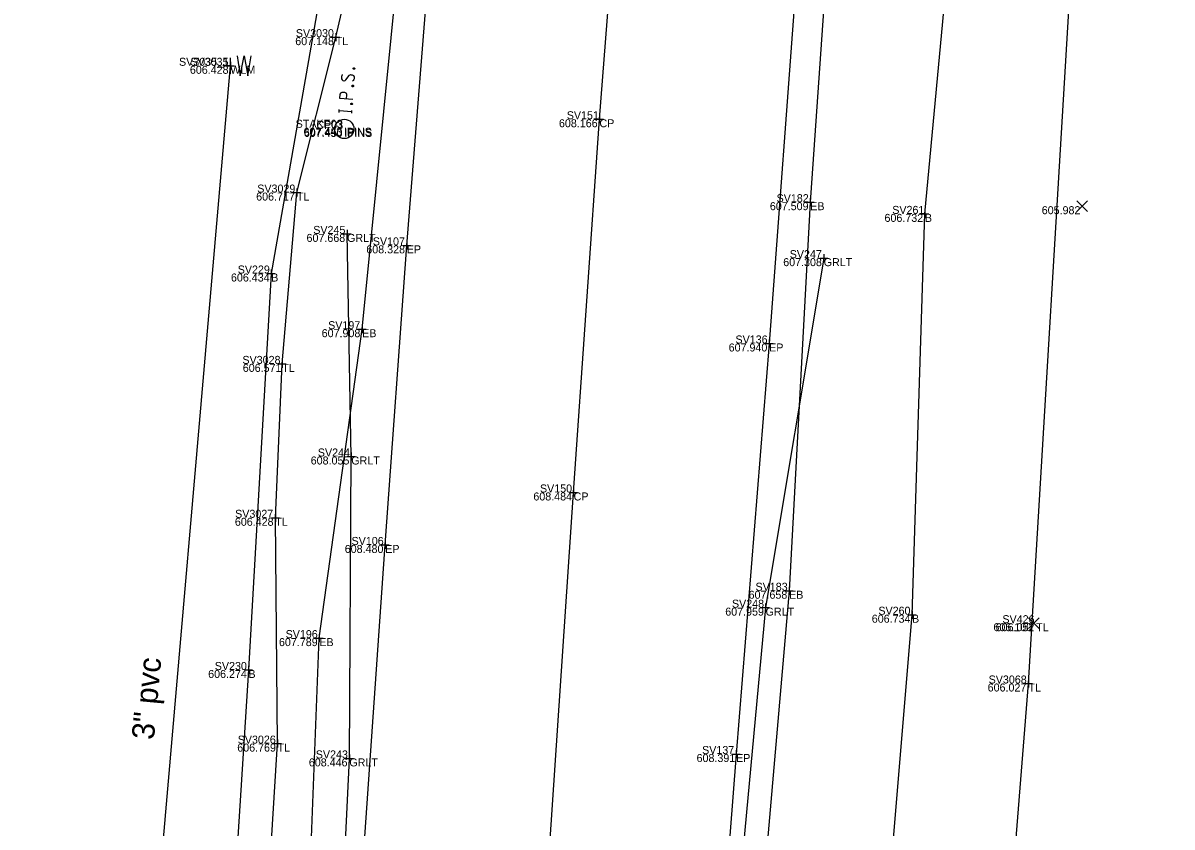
# Model space of a CAD drawing. Extents: x -2 to 1979875, y -2 to 232027.
# Drawn here: x 1978751.3 to 1978823.1, y 231412.1 to 231462.4 of the extents above; entities that cross this region are included whole.
import ezdxf

# ---------------------------------------------------------------- set-up
doc = ezdxf.new("R2010")
doc.units = 0
for name, color, linetype in [('_CIVIL_CONSTRUCTION', 7, 'Continuous'), ('GE_P_Alignment', 7, 'Continuous'), ('GE_P_Alignment_1000_Curve_Data', 7, 'Continuous'), ('GE_P_Alignment_100_Curve_Data', 7, 'Continuous'), ('GE_X_Alignment', 7, 'Continuous'), ('GE_X_Alignment_1000_Curve_Data', 7, 'Continuous'), ('GE_X_Alignment_1000_Stations', 7, 'Continuous'), ('GE_X_Alignment_100_Curve_Data', 7, 'Continuous'), ('GE_X_Alignment_100_Stations', 7, 'Continuous'), ('RW_X_CL', 7, 'Continuous'), ('SC_Scratch1', 7, 'Continuous'), ('SV_X_Random_Point', 7, 'Continuous'), ('UT_X_Water', 7, 'Continuous'), ('UT_X_Water_Cells', 7, 'Continuous'), ('UT_X_Water_Text', 7, 'Continuous')]:
    doc.layers.add(name, color=color, linetype=linetype)

msp = doc.modelspace()

# ---------------------------------------------------------------- linework, layer by layer
at = {"layer": 'GE_P_Alignment'}
for points in [[(1978861.689, 231782.415), (1978851.853, 231763.969), (1978841.987, 231745.294), (1978832.802, 231726.204), (1978823.63, 231707.125), (1978815.734, 231686.751), (1978809.08, 231664.461), (1978799.472, 231640.53), (1978791.914, 231616.771), (1978786.956, 231593.117), (1978782.497, 231568.131), (1978778.452, 231542.695), (1978775.331, 231517.531), (1978773.11, 231494.147), (1978771.443, 231473.021), (1978766.839, 231446.726), (1978765.415, 231421.944), (1978763.995, 231399.725), (1978762.317, 231376.717), (1978760.52, 231353.776), (1978758.484, 231331.627), (1978756.746, 231315.247), (1978755.236, 231305.004), (1978757.214, 231296.936)], [(1978796.543, 231298.857), (1978798.274, 231324.443), (1978800.704, 231350.055), (1978802.691, 231376.873), (1978804.911, 231401.653), (1978806.885, 231425.398), (1978807.692, 231450.453), (1978809.926, 231474.524), (1978811.781, 231491.704), (1978814.624, 231521.225), (1978818.445, 231546.214), (1978822.849, 231572.066), (1978827.059, 231594.68), (1978834.582, 231618.811), (1978841.486, 231643.192), (1978848.448, 231666.52), (1978859.661, 231691.186), (1978869.566, 231712.589), (1978880.404, 231735.407), (1978890.398, 231756.483), (1978895.241, 231765.92)]]:
    msp.add_lwpolyline(points, dxfattribs=at)
at = {"layer": 'GE_P_Alignment_1000_Curve_Data'}
for points in [[(1978733.125, 231254.651), (1978737.318, 231281.706), (1978740.694, 231296.926), (1978742.413, 231306.837), (1978748.228, 231322.336), (1978755.317, 231333.122), (1978758.78, 231344.165), (1978763.011, 231368.433), (1978764.4, 231379.716), (1978765.858, 231395.082), (1978767.238, 231417.341), (1978767.097, 231431.457), (1978767.532, 231441.077), (1978768.449, 231451.786), (1978770.871, 231461.5), (1978774.002, 231474.92), (1978775.889, 231489.026), (1978776.895, 231504.336), (1978777.94, 231514.653)], [(1978800.253, 231250.204), (1978805.284, 231291.391), (1978804.508, 231297.592), (1978804.78, 231306.073), (1978804.463, 231312.372), (1978805.146, 231324.315), (1978805.161, 231336.373), (1978807.189, 231350.111), (1978807.848, 231360.671), (1978809.086, 231373.348), (1978811.125, 231382.982), (1978814.162, 231421.098), (1978816.965, 231468.048), (1978822.427, 231510.515)]]:
    msp.add_lwpolyline(points, dxfattribs=at)
at = {"layer": 'GE_P_Alignment_100_Curve_Data'}
for points in [[(1978764.438, 231298.773), (1978765.712, 231320.829), (1978767.378, 231345.616), (1978768.807, 231367.39), (1978770.554, 231391.673), (1978771.722, 231416.416), (1978771.842, 231435.288), (1978771.576, 231449.202)], [(1978801.365, 231447.686), (1978797.734, 231425.84), (1978795.609, 231402.949), (1978794.056, 231378.448), (1978792.74, 231353.579), (1978790.842, 231329.19), (1978789.312, 231307.337), (1978788.697, 231297.789)]]:
    msp.add_lwpolyline(points, dxfattribs=at)
at = {"layer": 'GE_X_Alignment_1000_Curve_Data'}
msp.add_lwpolyline([(1978776.88, 231293.019), (1978778.313, 231315.451), (1978779.686, 231337.763), (1978781.119, 231360.475), (1978782.569, 231384.073), (1978784.079, 231408.548), (1978785.737, 231433.04), (1978787.352, 231456.369), (1978789.204, 231480.117), (1978791.477, 231503.648), (1978794.349, 231526.784), (1978797.796, 231550.891), (1978801.515, 231572.898), (1978806.442, 231596.208), (1978812.098, 231619.057), (1978818.629, 231640.775), (1978826, 231662.112), (1978835.057, 231685.412), (1978844.843, 231707.874), (1978854.489, 231728.841), (1978864.575, 231749.812), (1978877.222, 231774.568)], dxfattribs=at)
at = {"layer": 'GE_X_Alignment_1000_Stations'}
for points in [[(1978764.463, 231293.7), (1978765.973, 231315.536), (1978767.501, 231337.797), (1978768.95, 231360.619), (1978770.673, 231383.826), (1978772.372, 231407.034), (1978773.964, 231429.759), (1978775.312, 231448.487), (1978777.194, 231472.049), (1978779.086, 231494.381), (1978781.387, 231516.708), (1978784.451, 231540.773), (1978787.814, 231562.2), (1978793.416, 231590.474), (1978799.132, 231614.141), (1978805.307, 231636.271), (1978811.99, 231656.714), (1978821.006, 231681.034), (1978832.082, 231707.98), (1978843.434, 231732.641), (1978854.786, 231756.844), (1978866.633, 231780.181)], [(1978887.054, 231769.497), (1978875.688, 231747.111), (1978865.322, 231725.635), (1978856.257, 231705.079), (1978847.493, 231684.376), (1978839.463, 231663.377), (1978831.793, 231640.155), (1978824.647, 231616.117), (1978817.773, 231591.521), (1978812.873, 231567.295), (1978809.011, 231544.227), (1978805.416, 231519.882), (1978802.367, 231496.191), (1978799.68, 231465.625), (1978797.956, 231442.353), (1978795.891, 231416.691), (1978793.937, 231391.428), (1978792.627, 231370.424), (1978791.336, 231345.811), (1978789.97, 231322.684), (1978787.965, 231301.579), (1978787.711, 231292.48)]]:
    msp.add_lwpolyline(points, dxfattribs=at)
at = {"layer": 'GE_X_Alignment_100_Curve_Data'}
for p, q in [((1978770.871, 231461.75), (1978770.871, 231461.25)), ((1978770.621, 231461.5), (1978771.121, 231461.5)), ((1978770.871, 231461.5), (1978770.871, 231461.5)), ((1978764.036, 231459.71), (1978764.536, 231459.71)), ((1978764.286, 231459.96), (1978764.286, 231459.46)), ((1978764.286, 231459.71), (1978764.286, 231459.71)), ((1978787.102, 231456.369), (1978787.602, 231456.369)), ((1978787.352, 231456.619), (1978787.352, 231456.119)), ((1978787.352, 231456.369), (1978787.352, 231456.369)), ((1978768.199, 231451.786), (1978768.699, 231451.786)), ((1978768.449, 231452.036), (1978768.449, 231451.536)), ((1978768.449, 231451.786), (1978768.449, 231451.786)), ((1978800.271, 231451.185), (1978800.771, 231451.185)), ((1978800.521, 231451.435), (1978800.521, 231450.935)), ((1978800.521, 231451.185), (1978800.521, 231451.185)), ((1978807.442, 231450.453), (1978807.942, 231450.453)), ((1978807.692, 231450.703), (1978807.692, 231450.203)), ((1978807.692, 231450.453), (1978807.692, 231450.453)), ((1978771.576, 231449.452), (1978771.576, 231448.952)), ((1978771.326, 231449.202), (1978771.826, 231449.202)), ((1978771.576, 231449.202), (1978771.576, 231449.202)), ((1978775.312, 231448.737), (1978775.312, 231448.237)), ((1978775.062, 231448.487), (1978775.562, 231448.487)), ((1978775.312, 231448.487), (1978775.312, 231448.487)), ((1978801.115, 231447.686), (1978801.615, 231447.686)), ((1978801.365, 231447.936), (1978801.365, 231447.436)), ((1978801.365, 231447.686), (1978801.365, 231447.686)), ((1978766.589, 231446.726), (1978767.089, 231446.726)), ((1978766.839, 231446.976), (1978766.839, 231446.476)), ((1978766.839, 231446.726), (1978766.839, 231446.726)), ((1978772.272, 231443.246), (1978772.772, 231443.246)), ((1978772.522, 231443.496), (1978772.522, 231442.996)), ((1978772.522, 231443.246), (1978772.522, 231443.246)), ((1978797.706, 231442.353), (1978798.206, 231442.353)), ((1978797.956, 231442.603), (1978797.956, 231442.103)), ((1978797.956, 231442.353), (1978797.956, 231442.353)), ((1978767.282, 231441.077), (1978767.782, 231441.077)), ((1978767.532, 231441.327), (1978767.532, 231440.827)), ((1978767.532, 231441.077), (1978767.532, 231441.077)), ((1978771.592, 231435.288), (1978772.092, 231435.288)), ((1978771.842, 231435.538), (1978771.842, 231435.038)), ((1978771.842, 231435.288), (1978771.842, 231435.288)), ((1978785.487, 231433.04), (1978785.987, 231433.04)), ((1978785.737, 231433.29), (1978785.737, 231432.79)), ((1978785.737, 231433.04), (1978785.737, 231433.04)), ((1978767.097, 231431.707), (1978767.097, 231431.207)), ((1978766.847, 231431.457), (1978767.347, 231431.457)), ((1978767.097, 231431.457), (1978767.097, 231431.457)), ((1978773.714, 231429.759), (1978774.214, 231429.759)), ((1978773.964, 231430.009), (1978773.964, 231429.509)), ((1978773.964, 231429.759), (1978773.964, 231429.759)), ((1978798.953, 231426.897), (1978799.453, 231426.897)), ((1978799.203, 231427.147), (1978799.203, 231426.647)), ((1978799.203, 231426.897), (1978799.203, 231426.897)), ((1978797.484, 231425.84), (1978797.984, 231425.84)), ((1978797.734, 231426.09), (1978797.734, 231425.59)), ((1978797.734, 231425.84), (1978797.734, 231425.84)), ((1978806.635, 231425.398), (1978807.135, 231425.398)), ((1978806.885, 231425.648), (1978806.885, 231425.148)), ((1978806.885, 231425.398), (1978806.885, 231425.398)), ((1978769.594, 231423.935), (1978770.094, 231423.935)), ((1978769.844, 231424.185), (1978769.844, 231423.685)), ((1978769.844, 231423.935), (1978769.844, 231423.935)), ((1978765.415, 231422.194), (1978765.415, 231421.694)), ((1978765.165, 231421.944), (1978765.665, 231421.944)), ((1978765.415, 231421.944), (1978765.415, 231421.944)), ((1978813.912, 231421.098), (1978814.412, 231421.098)), ((1978814.162, 231421.348), (1978814.162, 231420.848)), ((1978814.162, 231421.098), (1978814.162, 231421.098)), ((1978766.988, 231417.341), (1978767.488, 231417.341)), ((1978767.238, 231417.591), (1978767.238, 231417.091)), ((1978767.238, 231417.341), (1978767.238, 231417.341)), ((1978771.722, 231416.666), (1978771.722, 231416.166)), ((1978795.641, 231416.691), (1978796.141, 231416.691)), ((1978795.891, 231416.941), (1978795.891, 231416.441)), ((1978795.891, 231416.691), (1978795.891, 231416.691)), ((1978771.472, 231416.416), (1978771.972, 231416.416)), ((1978771.722, 231416.416), (1978771.722, 231416.416))]:
    msp.add_line(p, q, dxfattribs=at)
at = {"layer": 'RW_X_CL'}
for points in [[(1978771.954, 231459.529), (1978771.955, 231459.556), (1978771.969, 231459.572), (1978771.995, 231459.587), (1978772.027, 231459.585), (1978772.051, 231459.567), (1978772.062, 231459.549), (1978772.06, 231459.522), (1978772.047, 231459.506), (1978772.021, 231459.491), (1978771.989, 231459.493), (1978771.965, 231459.511), (1978771.954, 231459.529)], [(1978771.292, 231459.164), (1978771.278, 231459.154), (1978771.265, 231459.139), (1978771.242, 231459.09), (1978771.226, 231459.031), (1978771.223, 231458.987), (1978771.222, 231458.97), (1978771.236, 231458.897), (1978771.27, 231458.834), (1978771.317, 231458.793), (1978771.367, 231458.778), (1978771.404, 231458.776), (1978771.456, 231458.783), (1978771.502, 231458.824), (1978771.711, 231459.114), (1978771.738, 231459.14), (1978771.764, 231459.149), (1978771.802, 231459.158), (1978771.84, 231459.155), (1978771.878, 231459.147), (1978771.902, 231459.14), (1978771.933, 231459.127), (1978771.957, 231459.114), (1978771.976, 231459.102), (1978771.993, 231459.084), (1978772.005, 231459.067), (1978772.016, 231459.044), (1978772.021, 231459.027), (1978772.024, 231458.977), (1978772.019, 231458.9), (1978772.003, 231458.852), (1978771.954, 231458.783), (1978771.914, 231458.742)], [(1978771.933, 231457.613), (1978771.135, 231457.667), (1978771.152, 231457.931), (1978771.16, 231457.958), (1978771.176, 231457.996), (1978771.189, 231458.011), (1978771.203, 231458.027), (1978771.236, 231458.047), (1978771.268, 231458.061), (1978771.319, 231458.069), (1978771.395, 231458.064), (1978771.419, 231458.057), (1978771.456, 231458.043), (1978771.499, 231458.018), (1978771.516, 231457.995), (1978771.528, 231457.978), (1978771.539, 231457.949), (1978771.542, 231457.905), (1978771.524, 231457.641)], [(1978771.881, 231458.44), (1978771.883, 231458.467), (1978771.896, 231458.483), (1978771.922, 231458.498), (1978771.954, 231458.496), (1978771.978, 231458.478), (1978771.989, 231458.46), (1978771.988, 231458.433), (1978771.974, 231458.417), (1978771.948, 231458.402), (1978771.916, 231458.405), (1978771.892, 231458.423), (1978771.881, 231458.44)], [(1978771.806, 231457.318), (1978771.807, 231457.346), (1978771.821, 231457.361), (1978771.847, 231457.376), (1978771.879, 231457.374), (1978771.903, 231457.356), (1978771.914, 231457.338), (1978771.913, 231457.311), (1978771.899, 231457.295), (1978771.873, 231457.281), (1978771.841, 231457.283), (1978771.817, 231457.301), (1978771.806, 231457.318)], [(1978771.076, 231456.798), (1978771.088, 231456.974)], [(1978771.88, 231456.833), (1978771.082, 231456.886)], [(1978771.875, 231456.745), (1978771.886, 231456.921)]]:
    msp.add_lwpolyline(points, dxfattribs=at)
msp.add_circle((1978771.409, 231455.764), 0.6, dxfattribs=at)
at = {"layer": 'SC_Scratch1'}
for points in [[(1978762.241, 231295.643), (1978763.575, 231312.653), (1978764.638, 231334.283), (1978765.818, 231356.042), (1978767.705, 231380.515), (1978769.009, 231402.257), (1978769.844, 231423.935), (1978772.522, 231443.246), (1978774.792, 231466.077), (1978776.974, 231489.898), (1978779.234, 231514.617), (1978782.489, 231539.582), (1978786.101, 231563.808), (1978790.249, 231586.35), (1978795.964, 231611.211), (1978802.838, 231634.974), (1978810.373, 231657.227), (1978818.1, 231678.589), (1978826.474, 231699.286), (1978835.162, 231719.41), (1978844.319, 231739.683), (1978854.914, 231761.571), (1978865.037, 231781.151)], [(1978888.808, 231768.485), (1978877.882, 231747.21), (1978866.825, 231724.389), (1978857.223, 231702.339), (1978848.244, 231681.507), (1978839.526, 231658.205), (1978831.772, 231633.737), (1978825.103, 231611.479), (1978819.562, 231589.918), (1978815.237, 231567.914), (1978810.741, 231543.659), (1978807.235, 231520.012), (1978805.099, 231498.598), (1978802.191, 231475.113), (1978800.521, 231451.185), (1978799.203, 231426.897), (1978797.071, 231402.161), (1978795.912, 231377.319), (1978794.635, 231352.241), (1978792.961, 231328.96), (1978791.062, 231305.225), (1978790.036, 231294.396)]]:
    msp.add_lwpolyline(points, dxfattribs=at)
at = {"layer": 'SV_X_Random_Point'}
for p, q in [((1978817.185, 231450.599), (1978817.851, 231451.267)), ((1978817.185, 231451.267), (1978817.851, 231450.599)), ((1978814.168, 231424.534), (1978814.834, 231425.202)), ((1978814.168, 231425.202), (1978814.834, 231424.534))]:
    msp.add_line(p, q, dxfattribs=at)
at = {"layer": 'UT_X_Water'}
msp.add_lwpolyline([(1978712.49, 231209.97), (1978714.812, 231240.893), (1978716.641, 231256.079), (1978724.417, 231285.176), (1978739.059, 231319.254), (1978749.995, 231338.561), (1978758.981, 231398.401), (1978764.286, 231459.71)], dxfattribs=at)
at = {"layer": 'UT_X_Water_Cells'}
for p, q in [((1978764.286, 231459.71), (1978763.81, 231459.71)), ((1978764.286, 231459.21), (1978764.286, 231460.21))]:
    msp.add_line(p, q, dxfattribs=at)
msp.add_lwpolyline([(1978764.708, 231460.335), (1978764.895, 231459.085), (1978765.141, 231460.335), (1978765.387, 231459.085), (1978765.584, 231460.335)], dxfattribs=at)

# ---------------------------------------------------------------- texts
at = {"layer": '_CIVIL_CONSTRUCTION'}
for s, p in [('607.148', (1978768.341, 231461)), ('606.428', (1978761.756, 231459.21)), ('606.428', (1978761.756, 231459.21)), ('608.166', (1978784.82, 231455.869)), ('607.443', (1978768.857, 231455.338)), ('607.450', (1978768.876, 231455.278)), ('607.450', (1978768.878, 231455.264)), ('606.717', (1978765.898, 231451.286)), ('607.509', (1978798, 231450.685)), ('605.982', (1978814.99, 231450.433)), ('606.732', (1978805.164, 231449.953)), ('607.668', (1978769.046, 231448.702)), ('608.328', (1978772.782, 231447.987)), ('607.308', (1978798.835, 231447.186)), ('606.434', (1978764.323, 231446.226)), ('607.908', (1978769.992, 231442.746)), ('607.940', (1978795.426, 231441.853)), ('606.571', (1978765.062, 231440.577)), ('608.055', (1978769.307, 231434.788)), ('608.484', (1978783.221, 231432.54)), ('606.428', (1978764.567, 231430.957)), ('608.480', (1978771.434, 231429.259)), ('607.658', (1978796.673, 231426.397)), ('607.959', (1978795.213, 231425.34)), ('606.734', (1978804.369, 231424.898)), ('606.100', (1978811.971, 231424.368)), ('606.052', (1978812.11, 231424.367)), ('607.789', (1978767.323, 231423.435)), ('606.274', (1978762.899, 231421.444)), ('606.027', (1978811.611, 231420.598)), ('606.769', (1978764.717, 231416.841)), ('608.446', (1978769.19, 231415.916)), ('608.391', (1978793.421, 231416.191))]:
    msp.add_text(s, height=0.5, dxfattribs=at).set_placement(p)
at = {"layer": 'GE_X_Alignment'}
for s, p in [('SV3030', (1978768.379, 231461.5)), ('SV3035_1', (1978761.078, 231459.71)), ('SV3035', (1978761.789, 231459.71)), ('SV151', (1978785.309, 231456.369)), ('STAKE03', (1978768.365, 231455.838)), ('CP03', (1978769.658, 231455.778)), ('CP03', (1978769.661, 231455.764)), ('SV3029', (1978765.967, 231451.786)), ('SV182', (1978798.42, 231451.185)), ('SV261', (1978805.649, 231450.453)), ('SV245', (1978769.467, 231449.202)), ('SV107', (1978773.187, 231448.487)), ('SV247', (1978799.24, 231447.686)), ('SV229', (1978764.745, 231446.726)), ('SV197', (1978770.397, 231443.246)), ('SV136', (1978795.851, 231442.353)), ('SV3028', (1978765.041, 231441.077)), ('SV244', (1978769.753, 231435.288)), ('SV150', (1978783.633, 231433.04)), ('SV3027', (1978764.584, 231431.457)), ('SV106', (1978771.859, 231429.759)), ('SV183', (1978797.105, 231426.897)), ('SV248', (1978795.631, 231425.84)), ('SV260', (1978804.781, 231425.398)), ('SV426', (1978812.533, 231424.867)), ('SV196', (1978767.739, 231423.935)), ('SV230', (1978763.311, 231421.944)), ('SV3068', (1978811.671, 231421.098)), ('SV3026', (1978764.744, 231417.341)), ('SV137', (1978793.766, 231416.691)), ('SV243', (1978769.624, 231416.416))]:
    msp.add_text(s, height=0.5, dxfattribs=at).set_placement(p)
at = {"layer": 'GE_X_Alignment_100_Stations'}
for s, p in [('TL', (1978770.871, 231461)), ('WL', (1978764.286, 231459.21)), ('WLM', (1978764.286, 231459.21)), ('CP', (1978787.352, 231455.869)), ('IPINS', (1978771.382, 231455.338)), ('IPINS', (1978771.406, 231455.278)), ('IPINS', (1978771.409, 231455.264)), ('TL', (1978768.449, 231451.286)), ('EB', (1978800.521, 231450.685)), ('B', (1978807.692, 231449.953)), ('GRLT', (1978771.576, 231448.702)), ('EP', (1978775.312, 231447.987)), ('GRLT', (1978801.365, 231447.186)), ('B', (1978766.839, 231446.226)), ('EB', (1978772.522, 231442.746)), ('EP', (1978797.956, 231441.853)), ('TL', (1978767.532, 231440.577)), ('GRLT', (1978771.842, 231434.788)), ('CP', (1978785.737, 231432.54)), ('TL', (1978767.097, 231430.957)), ('EP', (1978773.964, 231429.259)), ('EB', (1978799.203, 231426.397)), ('GRLT', (1978797.734, 231425.34)), ('B', (1978806.885, 231424.898)), ('TL', (1978814.638, 231424.367)), ('EB', (1978769.844, 231423.435)), ('B', (1978765.415, 231421.444)), ('TL', (1978814.162, 231420.598)), ('TL', (1978767.238, 231416.841)), ('GRLT', (1978771.722, 231415.916)), ('EP', (1978795.891, 231416.191))]:
    msp.add_text(s, height=0.5, dxfattribs=at).set_placement(p)
at = {"layer": 'UT_X_Water_Text'}
msp.add_text('3" pvc', height=1.4, rotation=84.7319, dxfattribs=at).set_placement((1978759.506, 231417.548))

doc.saveas('drawing.dxf')
